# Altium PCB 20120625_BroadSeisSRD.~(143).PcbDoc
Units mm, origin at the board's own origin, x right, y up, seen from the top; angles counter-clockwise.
Board outline 68.5 x 51 mm, 4 copper layers (Top Layer, Mid-Layer 1, Mid-Layer 2, Bottom Layer); 59 components, 43 nets, 186 pads, 37 vias.
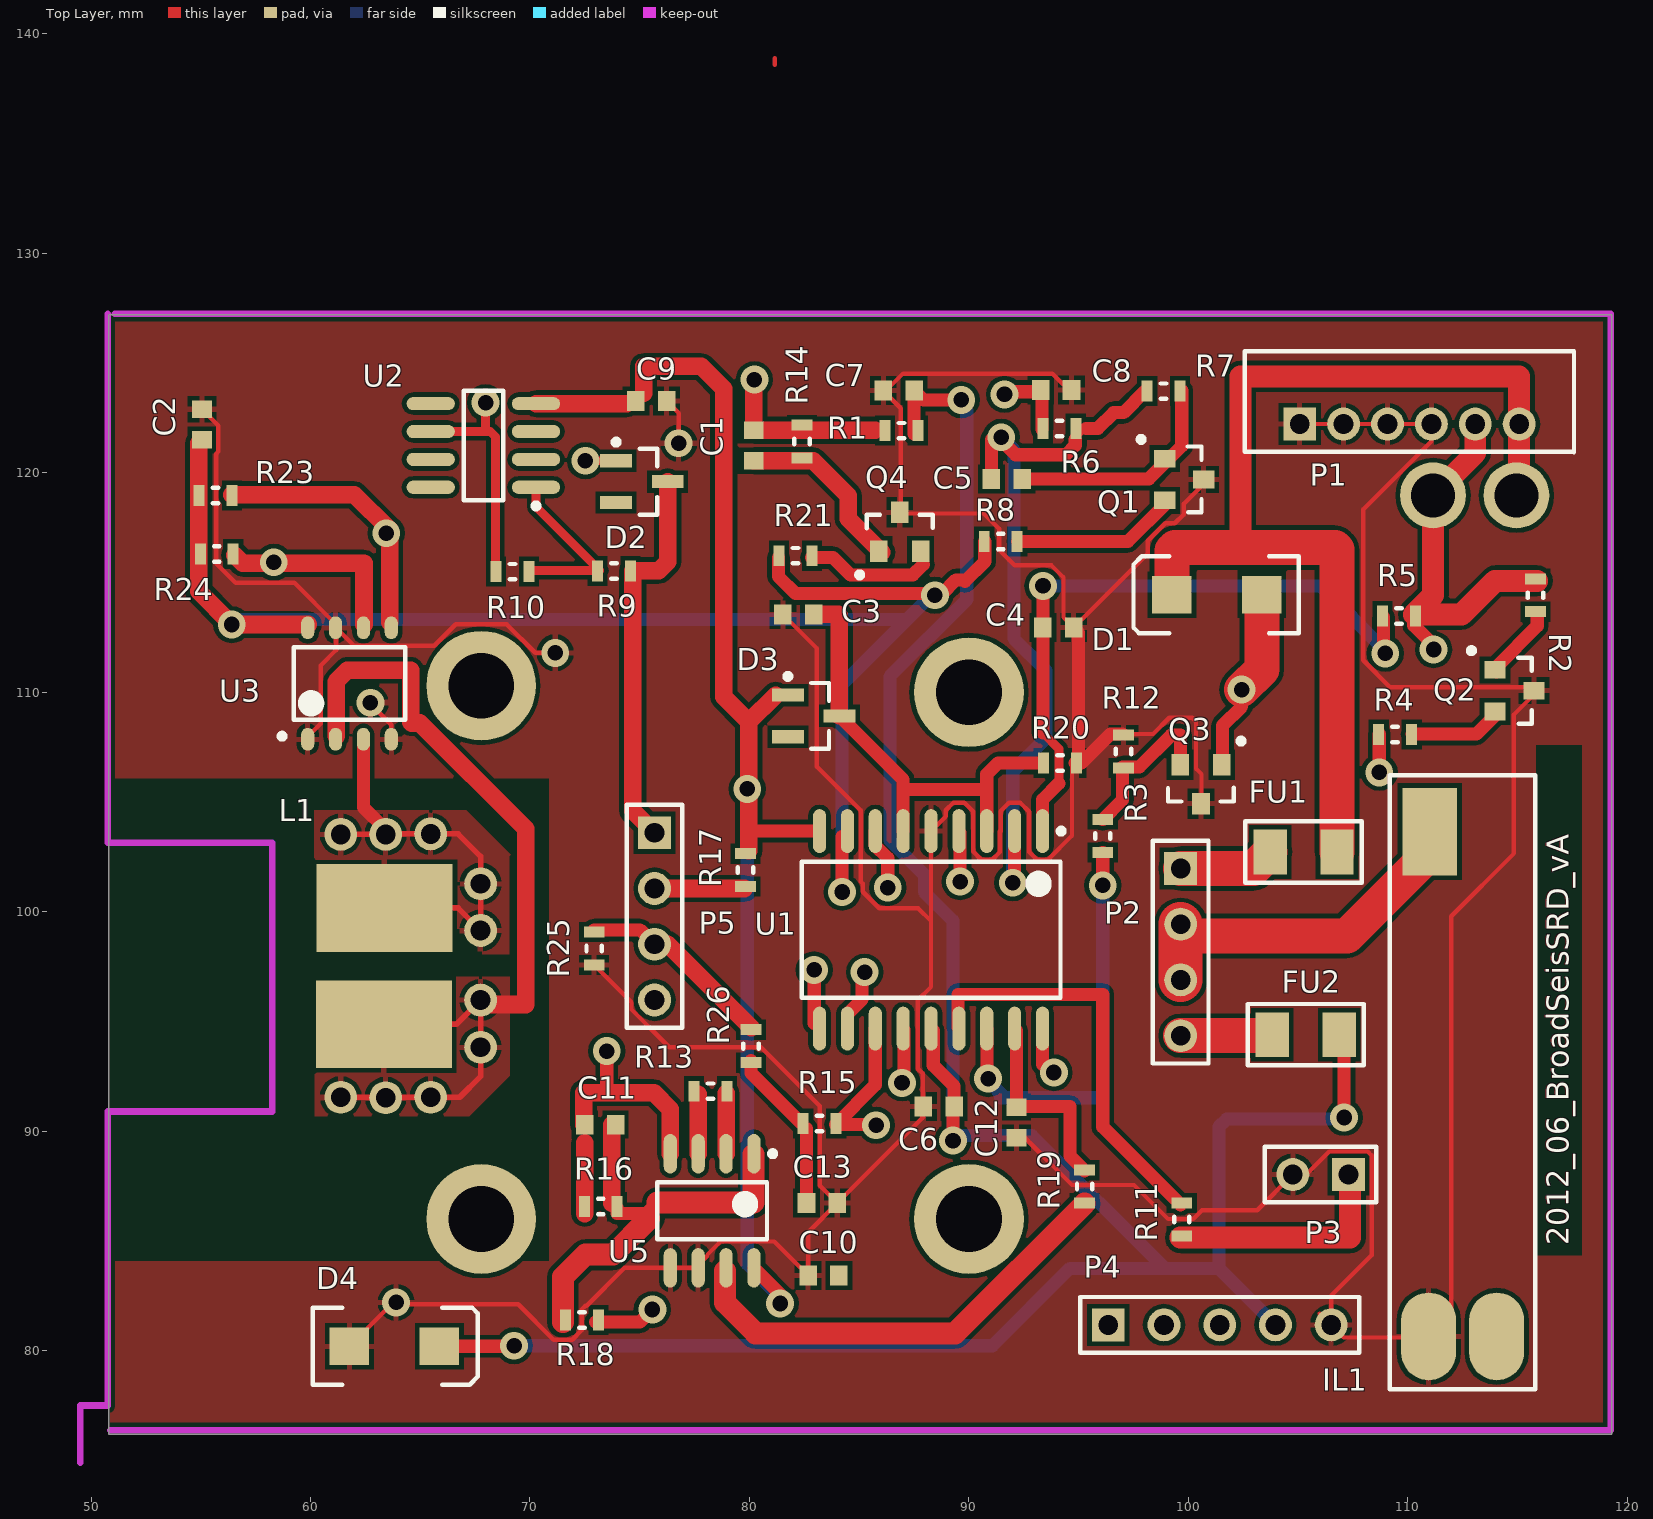
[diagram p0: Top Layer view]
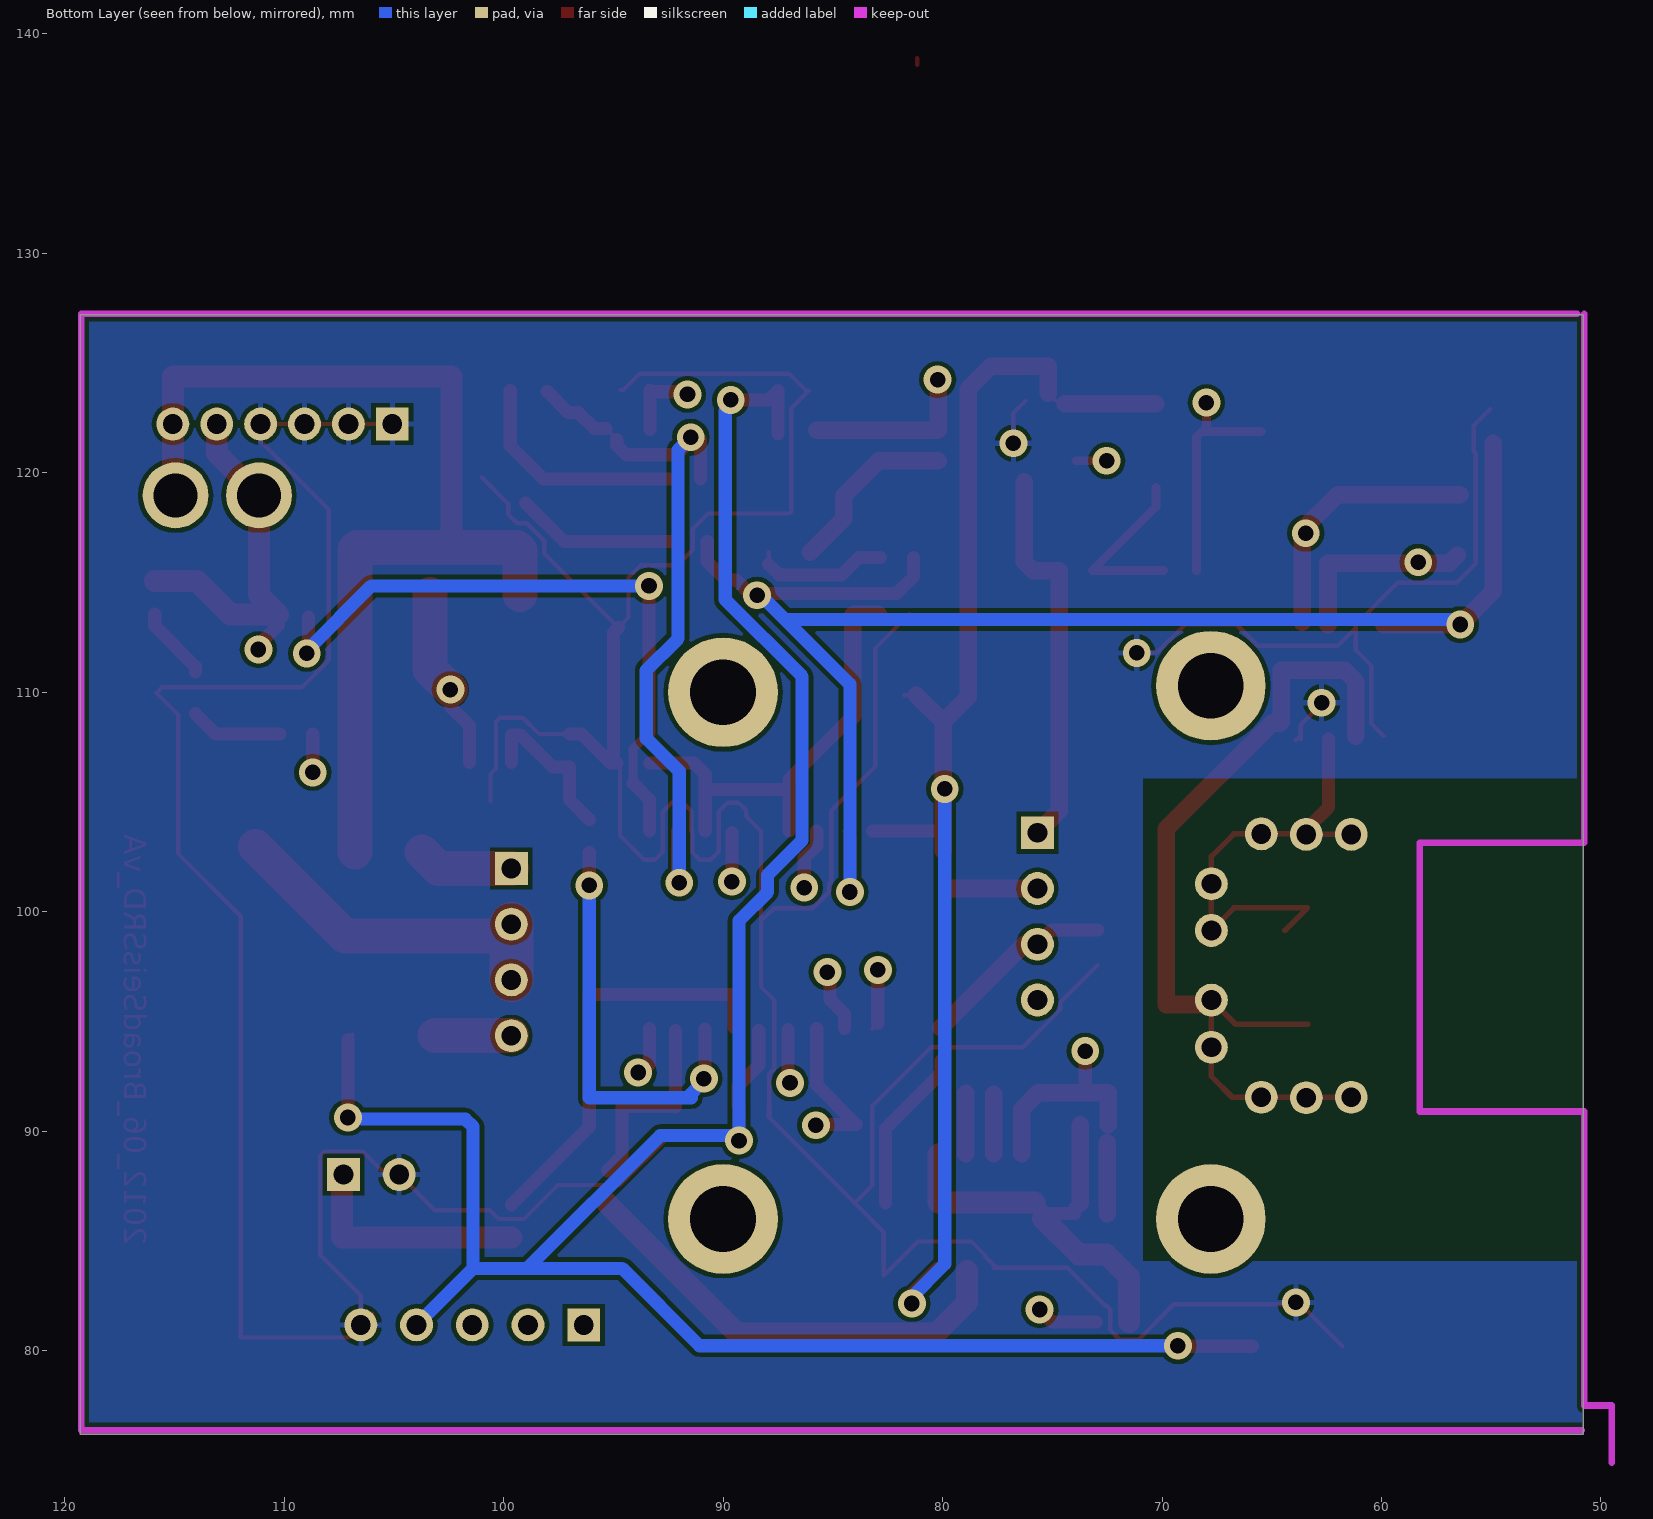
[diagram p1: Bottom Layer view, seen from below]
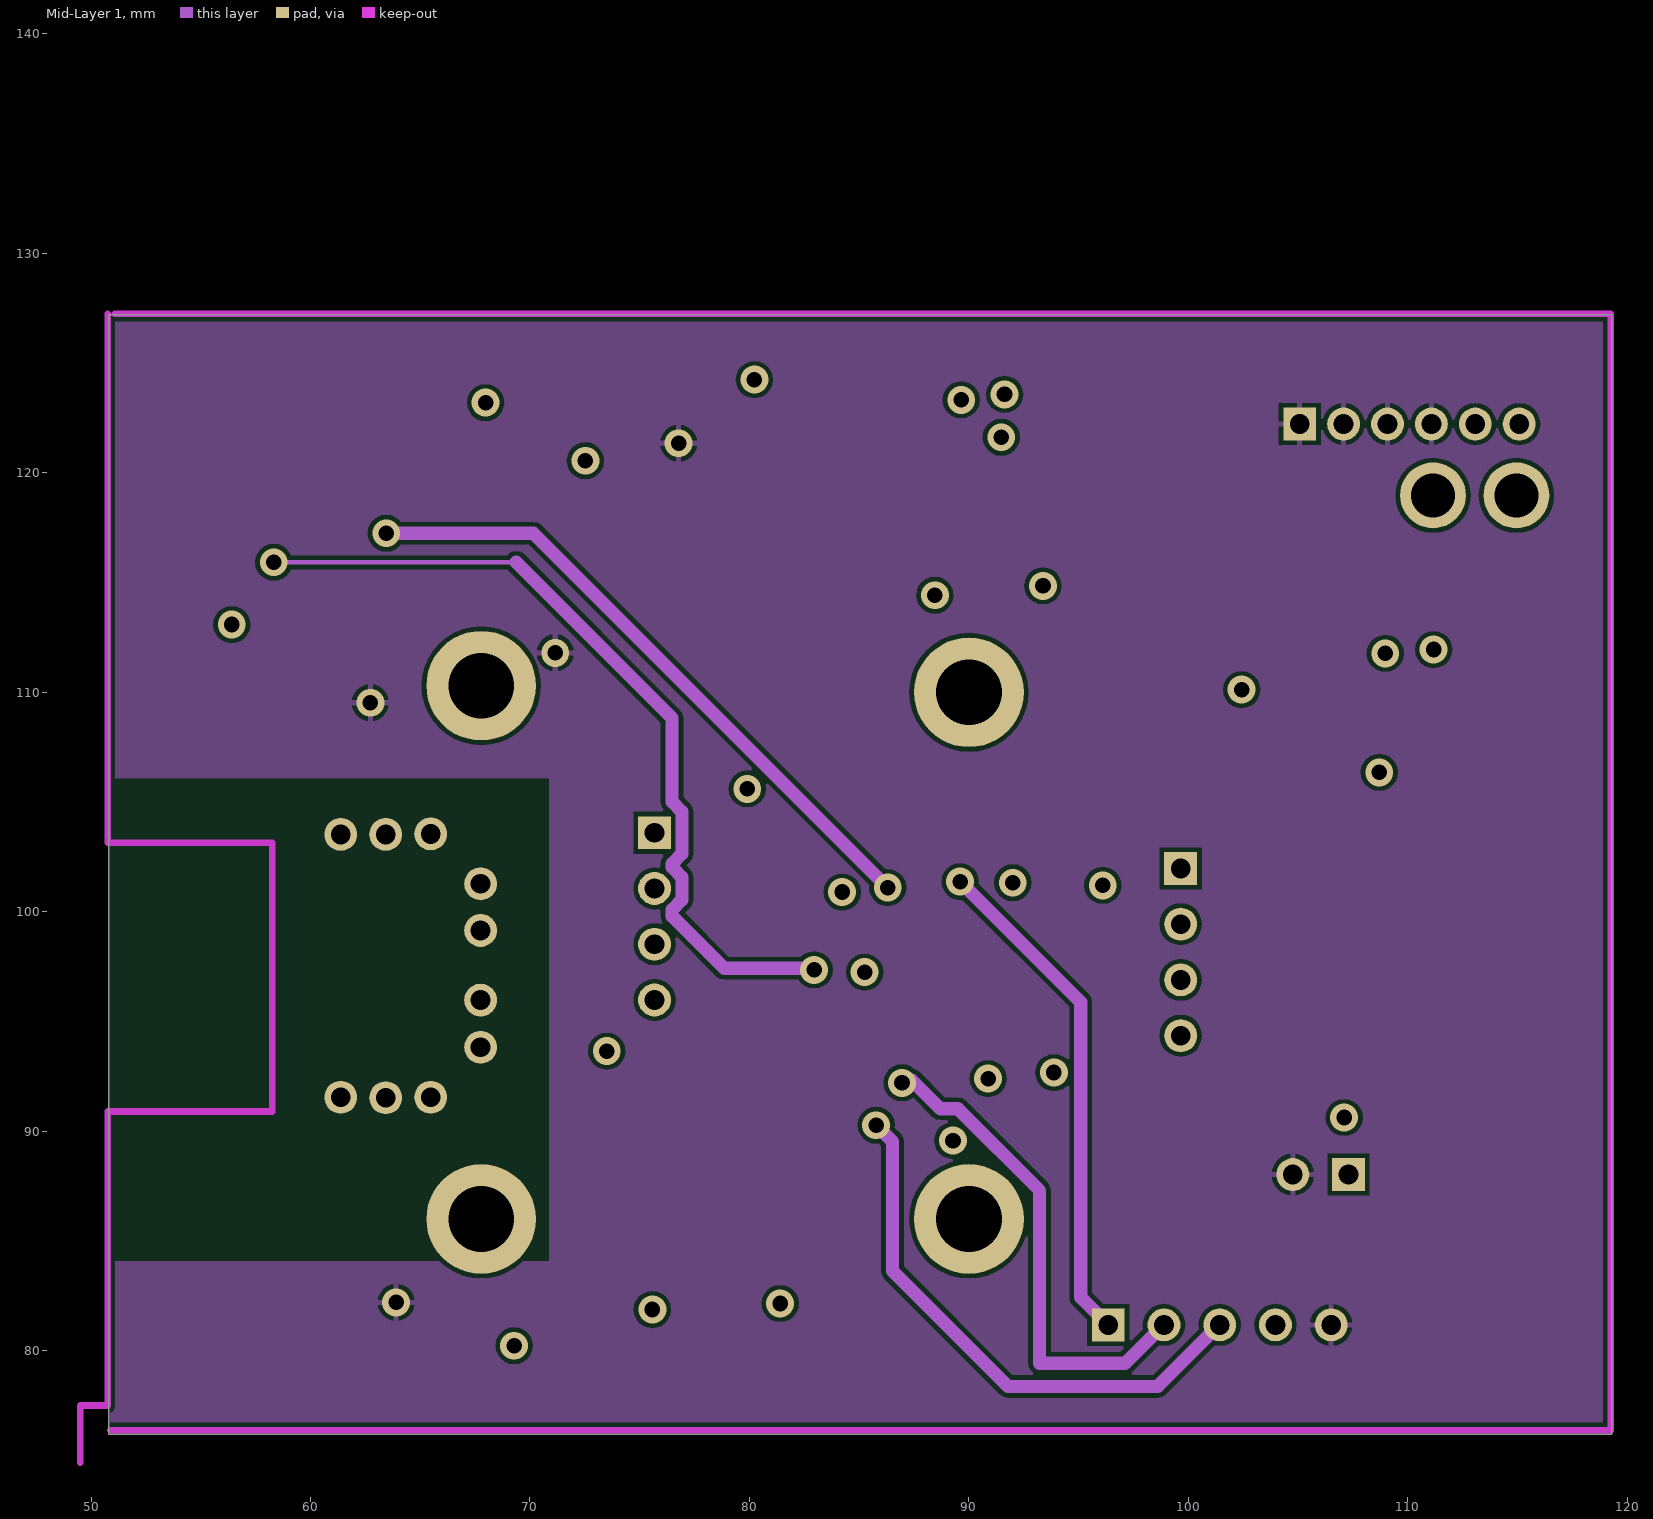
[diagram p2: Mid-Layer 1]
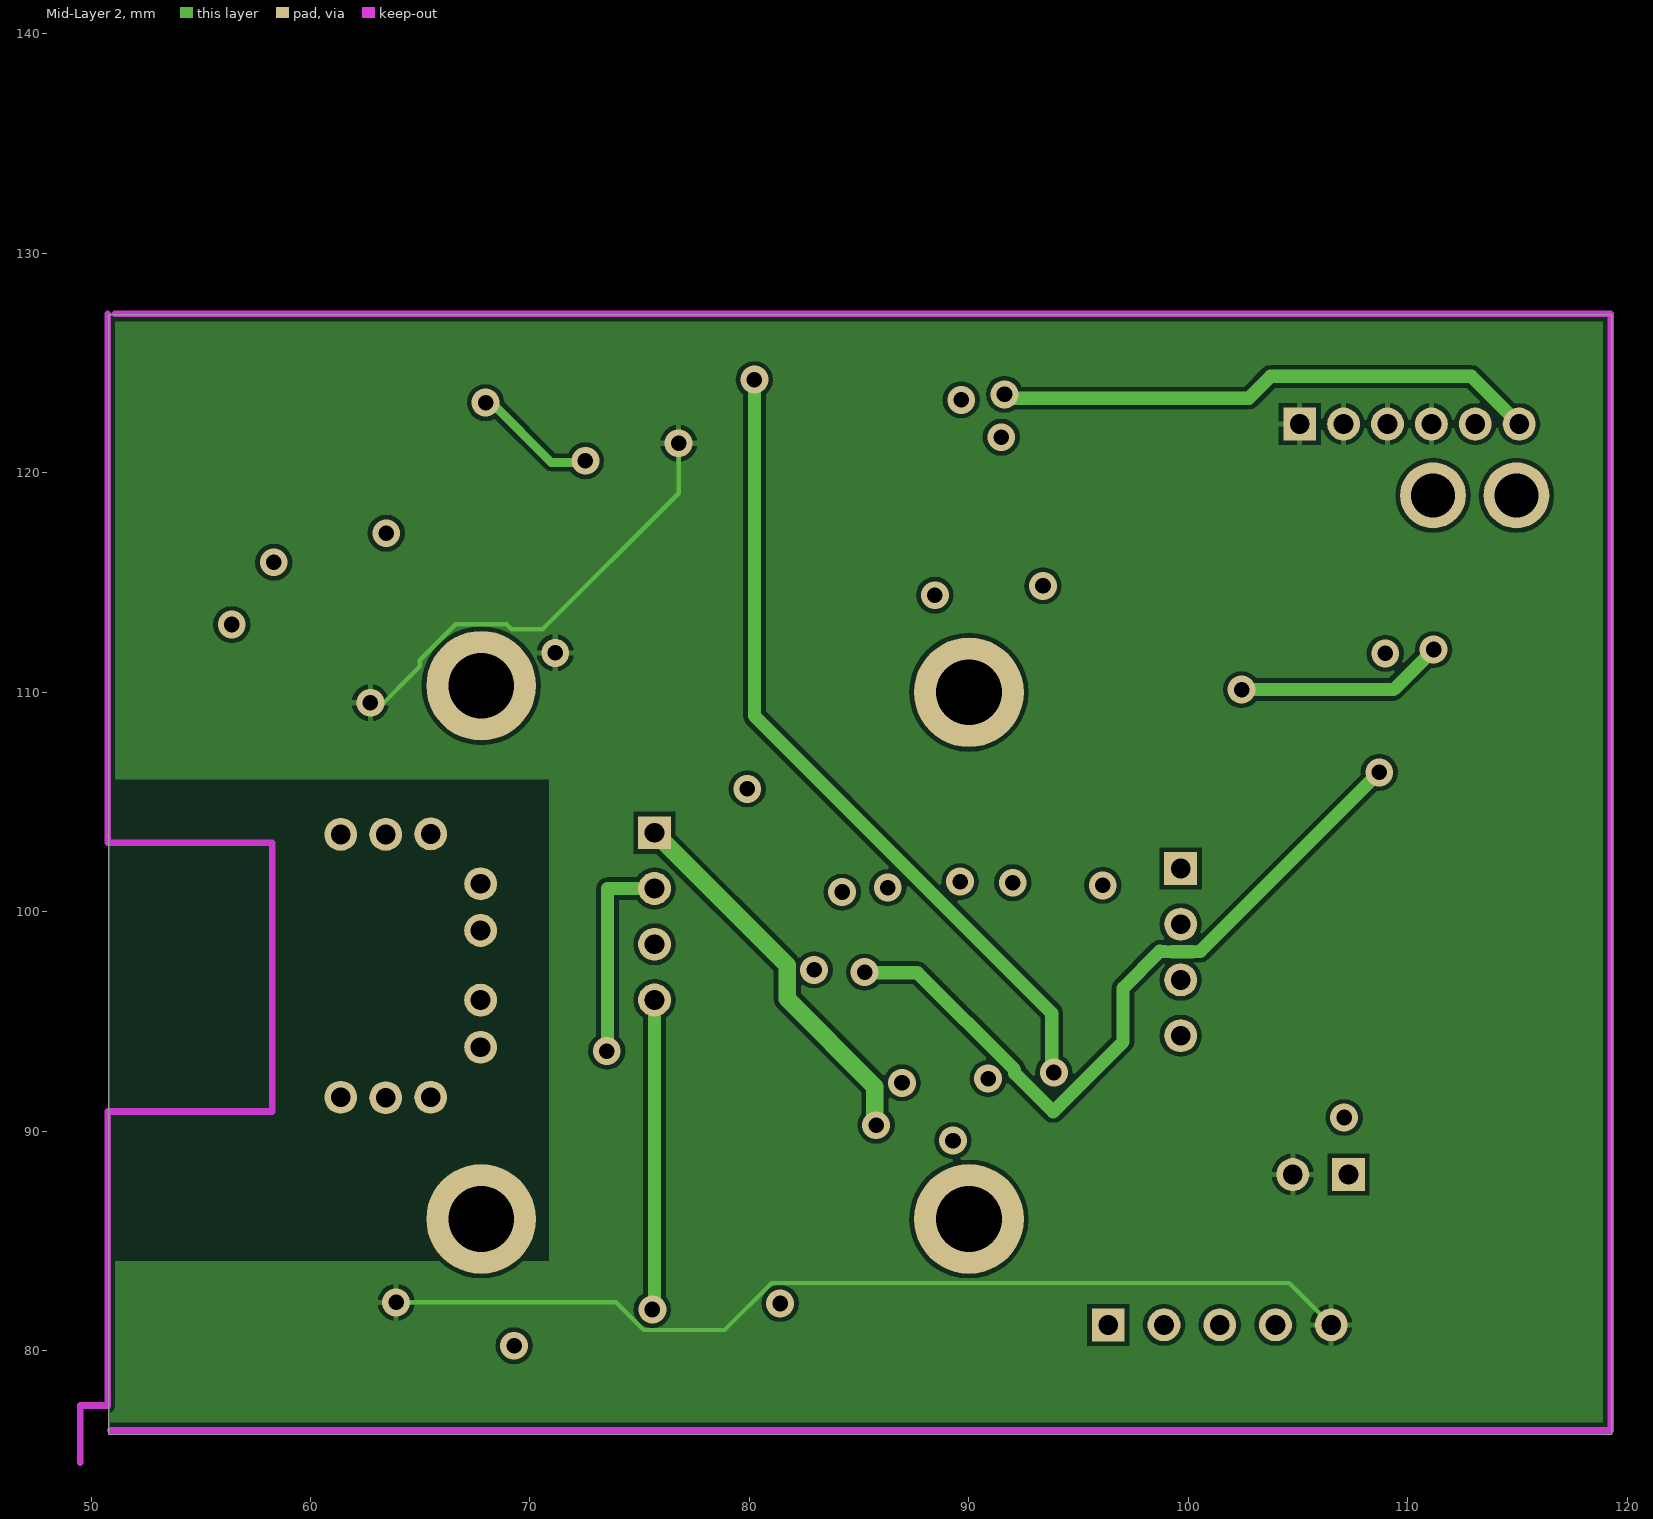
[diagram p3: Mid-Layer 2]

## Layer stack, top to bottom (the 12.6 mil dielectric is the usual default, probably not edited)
Top Layer: signal copper 0.0356
Dielectric: dielectric 0.32, FR-4, Dk 4.8
Mid-Layer 1: signal copper 0.0356
Dielectric: dielectric 0.32, FR-4, Dk 4.8
Mid-Layer 2: signal copper 0.0356
Dielectric: dielectric 0.32, FR-4, Dk 4.8
Bottom Layer: signal copper 0.0356

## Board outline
50.8,76.2 119.3,76.2 119.3,127.2 50.8,127.2

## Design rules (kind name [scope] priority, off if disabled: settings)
Clearance [All] p1: gap=0.2
HoleSize [All] p1: absolutevalues=TRUE maxlimit=5 minlimit=0.025 maxpercent=80.000 minpercent=20.000
PolygonConnect [All] p1: connectstyle=Relief reliefconductorwidth=0.254 reliefentries=4 polygonreliefangle="90 Angle"
RoomDefinition 2012_06_22_Sheet [InComponentClass('2012_06_22_Sheet')] p1: confinementstyle=ConfineIn formatcopy=TRUE lockcomponents=FALSE outline 49.281,128.725 49.412,128.593 121.35,128.593 121.35,74.737 121.114,74.5 49.15,74.5
RoutingVias [All] p1: holewidth=0.6 width=1 viastyle="Through Hole" minholewidth=0.711 minwidth=1.27 maxholewidth=0.711 maxwidth=1.27
SilkscreenOverComponentPads [All] p1: minsilkscreentomaskgap=0.254
SolderMaskExpansion [All] p1: expansion=0.102
Width [All] p1: maxlimit=2 minlimit=0.2 preferedwidth=0.6
26 further rules are at their usual default settings.

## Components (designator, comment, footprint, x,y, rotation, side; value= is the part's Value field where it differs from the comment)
C1 "Cap Semi" 1608[0603] 80.2,121.25 r90 top
C2 "Cap Semi" 1608[0603] 55.05,122.2 r270 top
C3 "Cap Semi" 1608[0603] 82.225,113.55 r0 top
C4 "Cap Semi" 1608[0603] 94.075,112.95 r180 top
C5 "Cap Semi" 1608[0603] 91.725,119.725 r180 top
C6 "Cap Semi" 1608[0603] 88.625,91.125 r0 top
C7 "Cap Semi" 1608[0603] 86.8,123.75 r0 top
C8 "Cap Semi" 1608[0603] 93.975,123.775 r180 top
C9 "Cap Semi" 1608[0603] 75.525,123.275 r180 top
C10 "Cap Semi" 1608[0603] 83.375,83.425 r0 top
C11 "Cap Semi" 1608[0603] 73.2,90.3 r180 top
C12 "Cap Semi" 1608[0603] 92.175,90.4 r90 top
C13 "Cap Semi" 1608[0603] 83.3,86.725 r180 top
D1 "RS1D" DiodeRS1D(recommendedfootprint) 101.3,114.45 r180 top
D2 "Diode BAS16" SOT-23_M 75.1,119.6 r0 top
D3 "Diode BAS16" SOT-23_M 82.925,108.925 r0 top
D4 "RS1D" DiodeRS1D(recommendedfootprint) 63.825,80.2 r0 top
FU1 "1A" FU(recommendedfootprint) 105.25,102.725 r0 top
FU2 "200mA" FU(recommendedfootprint) 105.35,94.4 r180 top
IL1 "ILS" ILS 113.95,103.65 r270 top
L1 "Inductor" INDC4532 63.375,97.525 r270 top
P1 "ConnectorToFB" "HIROSE DF3A-6P" 105.075,122.225 r0 top
P2 "Battery Pack pigtail" HDR1X4 99.65,101.975 r270 top
P3 "Connector to LED" HDR1X2 107.3,88.025 r180 top
P4 "Connector to Prog." HDR1X5 96.35,81.175 r0 top
P5 "Pressure Transducer pigtail" HDR1X4 75.675,103.6 r270 top
Q1 "NPN" transistor_SOT-23(recommendedfootprint) 99.9,119.7 r0 top
Q2 "NPN" transistor_SOT-23(recommendedfootprint) 114.95,110.075 r0 top
Q3 "MOSFET-IRLML" transistor_SOT-23(recommendedfootprint) 100.575,105.725 r270 top
Q4 "NPN" transistor_SOT-23(recommendedfootprint) 86.85,117.4 r90 top
R1 "Res3" J1-0603 86.925,121.925 r0 top
R2 "Res3" J1-0603 115.825,114.425 r90 top
R3 "Res3" J1-0603 96.1,103.45 r90 top
R4 "Res3" J1-0603 109.425,108.075 r0 top
R5 "Res3" J1-0603 109.6,113.475 r0 top
R6 "Res3" J1-0603 94.125,122.025 r180 top
R7 "Res3" J1-0603 98.875,123.725 r180 top
R8 "Res3" J1-0603 91.45,116.875 r0 top
R9 "Res3" J1-0603 73.825,115.525 r0 top
R10 "Res3" J1-0603 69.2,115.5 r180 top
R11 "Res3" J1-0603 99.7,85.975 r90 top
R12 "Res3" J1-0603 97.05,107.3 r270 top
R13 "Res3" J1-0603 78.225,91.825 r0 top
R14 "Res3" J1-0603 82.4,121.425 r90 top
R15 "Res3" J1-0603 83.2,90.35 r180 top
R16 "Res3" J1-0603 73.225,86.575 r180 top
R17 "Res3" J1-0603 79.825,101.9 r90 top
R18 "Res3" J1-0603 72.375,81.4 r180 top
R19 "Res3" J1-0603 95.275,87.475 r90 top
R20 "Res3" J1-0603 94.15,106.775 r180 top
R21 "Res3" J1-0603 82.1,116.225 r0 top
R23 "Res3" J1-0603 55.675,118.975 r0 top
R24 "Res3" J1-0603 55.725,116.3 r180 top
R25 "Res3" J1-0603 72.925,98.325 r90 top
R26 "Res3" J1-0603 80.075,93.875 r90 top
U1 "PIC16LF1827-I/SO" SOIC-SO18_L 88.275,99.175 r270 top
U2 "LM334D" SO8_N 67.875,121.25 r180 top
U3 "M24LR64" SO8N_N 61.775,110.4 r90 top
U5 "AD620BR" R-8D_N 78.3,86.375 r270 top

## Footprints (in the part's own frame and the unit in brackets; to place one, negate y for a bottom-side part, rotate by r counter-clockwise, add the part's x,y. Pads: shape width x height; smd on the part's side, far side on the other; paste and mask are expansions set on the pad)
1608[0603] [mm] "Chip Capacitor, Body 1.6x0.8mm, IPC High Density"
  rect 0.8x0.9 smd: 1(-0.7,0) 2(0.7,0)
  body extent -0.87,-0.48 0.87,0.48, height 1.3
DiodeRS1D(recommendedfootprint) [mm] "DO-214-AB/SMC; 2 C-Bend Leads; Body 7.9 x 5.9 mm, inc. leads (LxW)"
  rect 1.8x1.7 smd: 1(-2.05,0) 2(2.05,0)
  silkscreen extent -3.73,-1.75 3.8,1.75
FU(recommendedfootprint) [mm] "Thru-Hole; 2 Leads"
  rect 1.52x2.03 smd: 1(-1.525,0) 2(1.525,0)
  silkscreen extent -2.65,-1.4 2.65,1.4
HDR1X2 [mm] "Connector; Header; 2 Position"
  rect 1.5x1.5 hole 0.9: 1(0,0)
  round 1.5 hole 0.9: 2(2.54,0)
  silkscreen extent -1.27,-1.27 3.81,1.27
HDR1X4 [mm] "Connector; Header; 4 Position"
  rect 1.5x1.5 hole 0.9: 1(0,0)
  round 1.5 hole 0.9: 2(2.54,0) 3(5.08,0) 4(7.62,0)
  silkscreen extent -1.27,-1.27 8.89,1.27
HDR1X5 [mm] "Connector; Header; 5 Position"
  rect 1.5x1.5 hole 0.9: 1(0,0)
  round 1.5 hole 0.9: 2(2.54,0) 3(5.08,0) 4(7.62,0) 5(10.16,0)
  silkscreen extent -1.27,-1.27 11.43,1.27
"HIROSE DF3A-6P" [mm] "Connector; Header; 6 Position"
  rect 1.5x1.5 hole 0.9: 1(0,0)
  round 1.5 hole 0.9: 2(2,0) 3(4,0) 4(6,0) 5(8,0) 6(10,0)
  round 3 hole 2: 5(6.075,-3.25) 6(9.875,-3.25)
  Top Layer lines w0.254: 9.875,-3.25 10,-2.75
  Top Layer lines w1: 6.075,-3.25 8,-1.325 8,0 ; 10,-2.75 10,0
  silkscreen extent -2.5,-1.29 12.5,3.32
ILS [mm]
  rect 4x2.5 smd: 1(0,-2.95)
  oval 4x2.5 smd: 2(23,-3) 3(23,0.1)
  silkscreen extent -2.58,-4.77 25.4,1.85
INDC4532 [mm] "Chip Inductor, Body 4.5x3.2mm, IPC High Density"
  round 1.5 hole 0.9: 1(-6.025,2.1) 1(-6,0.05) 1(-6,-2) 1(-3.75,4.375) 1(-1.625,4.375) 2(1.55,4.375) 2(3.7,4.375) 2(5.975,2.1) 2(5.975,-2) 2(6,0.05)
  rect 4x6.2 smd: 1(-2.65,0) 2(2.65,-0.025)
  Top Layer lines w0.254: -6,-2 -6,0.05 -6.025,0.075 -6.025,2.1 -6.025,3.35 -5,4.375 -3.75,4.375 -1.625,4.375 -2.65,3.35 -2.65,0 -1.625,1.025
J1-0603 [mm] "Chip Resistor, Body 1.6x0.8mm, IPC High Density"
  rect 0.5x0.95 smd: 1(-0.75,0) 2(0.75,0)
  silkscreen extent -0.13,-0.35 0.13,0.35, body extent -0.85,-0.48 0.85,0.48, height 0.9
R-8D_N [mm] "SOIC, 8-Leads, Body 4.9x3.9mm, Pitch 1.27mm, IPC Medium Density"
  oval 1.8x0.6 smd: 1(-2.6,1.905) 2(-2.6,0.635) 3(-2.6,-0.635) 4(-2.6,-1.905) 5(2.6,-1.905) 6(2.6,-0.635) 7(2.6,0.635) 8(2.6,1.905)
  silkscreen extent -2.72,-2.5 1.3,2.88, body extent -2,-2.5 2,2.5, height 2.59
SO8_N [mm] "SOIC, 8-Leads, Body 4.9x3.9mm, Pitch 1.27mm, IPC Medium Density"
  oval 2.2x0.6 smd: 1(-2.4,1.905) 2(-2.4,0.635) 3(-2.4,-0.635) 4(-2.4,-1.905) 5(2.4,-1.905) 6(2.4,-0.635) 7(2.4,0.635) 8(2.4,1.905)
  silkscreen extent -2.53,-2.5 0.9,2.88, body extent -1.95,-2.45 1.95,2.45, height 1.75
SO8N_N [mm] "SOP, 8-Leads, Body 5.3x5.3mm, Pitch 1.27mm, IPC Medium Density"
  oval 1.04x0.6 smd: 1(-2.54,1.905) 2(-2.54,0.635) 3(-2.54,-0.635) 4(-2.54,-1.905) 5(2.54,-1.905) 6(2.54,-0.635) 7(2.54,0.635) 8(2.54,1.905)
  silkscreen extent -2.52,-2.54 1.65,3.2, body extent -2.29,-2.54 2.29,2.54, height 2.13
SOIC-SO18_L [mm] "SOIC, 18-Leads, Body 11.5x7.5mm, Pitch 1.27mm, IPC High Density"
  oval 2x0.6 smd: 1(-4.5,5.08) 2(-4.5,3.81) 3(-4.5,2.54) 4(-4.5,1.27) 5(-4.5,0) 6(-4.5,-1.27) 7(-4.5,-2.54) 8(-4.5,-3.81) 9(-4.5,-5.08) 10(4.5,-5.08) 11(4.5,-3.81) 12(4.5,-2.54) 13(4.5,-1.27) 14(4.5,0) 15(4.5,1.27) 16(4.5,2.54) 17(4.5,3.81) 18(4.5,5.08)
  silkscreen extent -4.62,-5.9 3.1,6.06, body extent -3.8,-5.95 3.8,5.95, height 2.65
SOT-23_M [mm] "SOT23, 3-Leads, Body 2.9x1.3mm, Pitch 0.95mm, Lead Span 2.5mm, IPC Low Density"
  rect 1.45x0.6 smd: 1(-1.175,0.95) 2(-1.175,-0.95) 3(1.175,0)
  silkscreen extent -1.3,-1.5 0.7,1.92, body extent -0.7,-1.5 0.7,1.5, height 1.1
transistor_SOT-23(recommendedfootprint) [mm] "SOT23, 3-Leads, Body 2.9x1.3mm, Pitch 0.95mm, Lead Span 2.5mm, IPC Low Density"
  rect 0.972x0.802 smd: 1(-0.975,0.95) 2(-0.975,-0.95) 3(0.8,0)
  silkscreen extent -2.17,-1.5 0.7,1.95, body extent -0.7,-1.5 0.7,1.5, height 1.1

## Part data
C1 C2 C3 C4 C5 C6 C7 C8 C9 C10 C11 C12 C13: "Capacitor (Semiconductor SIM Model)"
D1 D4: library part Diode, "Default Diode"
D2 D3: "Silicon Switching Diode for High-Speed Switching"
FU1 FU2: library part "Fuse 1", "Fuse"
IL1: "SPDT Subminiature Toggle Switch, Right Angle Mounting, Vertical Actuation"
P1: "Header, 6-Pin"
P2 P5: "Header, 4-Pin"
P3: "Header, 2-Pin"
P4: "Header, 5-Pin"
Q1 Q2 Q4: "NPN Bipolar Transistor"
Q3: "N-Channel MOSFET"
R1 R2 R3 R4 R5 R6 R7 R8 R9 R10 R11 R12 R13 R14 R15 R16 R17 R18 R19 R20 R21 R23 R24 R25 R26: "Resistor"
U1: "EPROM-Based 8-Bit CMOS Microcontroller, 25 Bytes RAM, 4 MHz, 18-Pin SOIC, 3.0 to 5.5V Supply Range, Extended Temperature"
U2: "Three Terminal Adjustable Current Source"
U3: "32 Kbit Serial I²C Bus EEPROM"
U5: "Low-Cost, Low-Power Instrumentation Amplifier"

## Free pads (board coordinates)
  round 5 hole 3: 1(67.775,86) 1(67.775,110.3) 1(90,86) 1(90,110)

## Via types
v1: diameter 1.27, hole 0.711, Top Layer to Bottom Layer, 37 vias

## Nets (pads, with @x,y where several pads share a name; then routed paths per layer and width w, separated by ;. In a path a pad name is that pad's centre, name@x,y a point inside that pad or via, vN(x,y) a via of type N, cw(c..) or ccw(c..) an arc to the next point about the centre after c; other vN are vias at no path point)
ACTIVATION+: FU1.1 P2.1 | length 4.4
  Top Layer w1.6: P2.1 102.975,101.975 FU1.1
ANA_PRESSURE: C12.2 R19.2 U1.17 | length 9.3
  Top Layer w0.2: U1.17 U1.17@92.175,94.585 ; C12.2 C12.2@92.2,91.125
  Top Layer w0.6: C12.2 U1.17@92.175,94.585 ; C12.2@92.2,91.125 94.6,91.125 94.6,88.875 R19.2@95.275,88.2
B7: P4.2 U1.13 | length 25.1
  Top Layer w0.2: U1.13 U1.13@87.05,94.63
  Top Layer w0.6: v1(86.954,92.204) 86.954,92.454 87.05,92.55 U1.13@87.05,94.63
  Mid-Layer 1 w0.6: v1@86.95,92.325 87.4,92.325 88.7,91.025 89.5,91.025 93.225,87.3 93.225,79.425 97.115,79.425 P4.2@98.878,81.187
CHECK-FIRE: R4.1 U1.11 | length 38.6
  Top Layer w0.2: v1@85.135,97.135 v1(85.25,97.25)
  Top Layer w0.6: U1.11 84.465,95.34 85.135,96.01 v1@85.135,97.135 ; v1(108.7,106.35) R4.1@108.7,108.1
  Mid-Layer 2 w0.6: v1@85.325,97.225 87.655,97.225 92.085,92.795 92.085,92.64 93.838,90.887 97.025,94.075 97.025,96.525 98.7,98.2 99.262,98.175 100.187,98.175 100.55,98.2 v1(108.7,106.35)
COIL1: L1.1 U3.3 | length 4.8
  Top Layer w0.254: L1.1@63.425,103.525 L1.1@63.425,103.75
  Top Layer w0.6: U3.3 62.41,104.765 L1.1@63.425,103.75
COIL2: L1.2 U3.2 | length 40.9
  Top Layer w0.2: 61.165,110.49 61.2,110.525
  Top Layer w0.254: L1.2@61.375,91.55 65.475,91.55 66.8,91.55 67.75,92.5 67.75,93.825 67.75,95.975 66.65,94.875 L1.2@63.35,94.875
  Top Layer w0.8: U3.2@61.165,108.01 61.165,110.49 ; 61.2,110.525 61.675,111 64.575,111 64.575,108.633 64.605,108.603 64.972,108.603 69.8,103.775 69.8,95.775 67.95,95.775 L1.2@67.75,95.975
FB1: C8.2 D1.2 FU1.2 P1.6 R6.2 | length 75.1
  Top Layer w0.2: 99.25,116.45 99.4,116.6 ; 102.325,116.6 102.375,116.65 ; 106.675,116.6 106.775,116.5
  Top Layer w0.6: v1(91.625,123.575) 91.45,123.575 91.375,123.5 91.6,123.5 91.8,123.7 C8.2@93.275,123.7 ; R6.2@93.325,121.975 C8.2@93.325,123.775
  Top Layer w1: 102.375,116.65 102.375,124.4 115.075,124.4 P1.6@115.075,122.225
  Top Layer w1.6: D1.2 99.25,116.45 ; 99.4,116.6 102.325,116.6 106.675,116.6 ; FU1.2 106.775,116.5
  Mid-Layer 2 w0.6: v1@91.65,123.775 92.025,123.4 102.75,123.4 103.75,124.4 112.9,124.4 P1.6@115.075,122.225
FB2: D1.1 P1.5 Q3.1 R2.2 R5.2 | length 31.7
  Top Layer w0.6: Q3.1@101.55,106.8 101.55,108.475 102.425,109.35 v1(102.425,110.125) ; R5.2@110.275,113.55 110.275,113.05 v1@111.175,112.15
  Top Layer w1: P1.5@111.15,118.975 111.15,114.425 110.275,113.55 112.45,113.55 113.975,115.075 R2.2@115.9,115.075
  Top Layer w1.6: v1(102.425,110.125) 103.35,111.05 D1.1
  Mid-Layer 2 w0.6: v1(102.425,110.125) 109.35,110.125 v1(111.175,111.95)
FIRE: R3.1 U1.16 | length 19.8
  Top Layer w0.2: U1.16 U1.16@90.825,94.665
  Top Layer w0.6: U1.16@90.825,94.665 90.825,92.15 90.9,92.225 90.95,92.225 90.875,92.3 v1(90.875,92.4) ; v1(96.1,101.2) R3.1
  Bottom Layer w0.6: v1@90.825,92.15 90.9,92.225 90.95,92.225 91.575,91.6 ; 91.45,91.525 96.1,91.525 v1(96.1,101.2)
FLASH_LED: R11.2 U1.15 | length 19.2
  Top Layer w0.2: U1.15@89.5,94.72 U1.15
  Top Layer w0.6: U1.15@89.5,94.72 89.5,96.225 96.1,96.225 96.1,90.2 R11.2@99.65,86.65
GND: C2.1 C3.1 C4.1 C6.1 C7.1 C8.1 C9.1 C10.1 C12.1 C13.1 D4.1 IL1.2 P1.1 P1.2 P1.3 P1.4 P3.2 P4.5 Q1.3 Q2.3 Q3.3 Q4.3 R12.1 R20.1 R25.1 U1.5 U3.1 U3.4 U3.7 U5.5 U5.6 | length 348
  Top Layer w0.2: C2.1 55.8,122.15 55.8,120.976 55.7,120.876 55.7,115.876 56.586,114.99 59.265,114.99 61.165,113.09 U3.7@61.165,112.94 ; U3.1@59.895,108.01 60.465,108.58 60.465,111.225 61.165,111.925 U3.7@61.165,112.94 ; D4.1 63.687,82.113 69.463,82.113 71.076,80.5 71.924,80.5 72.35,80.926 72.35,81.874 72.526,82.05 72.581,82.05 74.306,83.775 U5.5 77.535,83.775 U5.6@77.6,83.84 ; v1@62.575,109.325 62.875,109.325 63.68,108.52 U3.4 ; U3.4@63.705,108.01 U3.4@63.9,107.815 ; v1(71.15,111.8) 70.235,111.8 68.935,113.1 66.615,113.1 65.635,112.12 61.985,112.12 U3.7@61.165,112.94 ; R25.1 74.625,95.875 74.625,95.545 76.345,93.825 80.524,93.825 83.2,91.149 83.2,87.525 C13.1 ; C9.1 76.775,122.725 v1(76.775,121.35) ; U5.6@77.6,83.775 U5.6@77.6,83.84 ; U5.6 U5.6@77.6,83.84 ; C3.1 83.075,112 83.075,106.614 85.065,104.624 85.065,101.382 85.16,101.287 85.16,100.918 85.913,100.165 87.685,100.165 88.275,99.575 ; 87.925,90.65 C6.1 C6.1@87.889,91.089 ; C12.1@92.075,89.8 C12.1 92.551,89.7 94.701,87.55 97.526,87.55 99.076,86 100.224,86 100.624,86.4 103.135,86.4 P3.2 105.376,88.025 106.426,89.075 108.174,89.075 108.35,88.899 108.35,84.35 106.51,82.51 P4.5 ; C8.1 94.549,123.775 93.799,124.525 87.001,124.525 86.226,123.75 C7.1 86.9,122.95 86.9,118.225 86.975,118.15 90.674,118.15 91.375,117.449 91.375,116.501 92.091,115.785 93.762,115.785 94.31,115.237 94.31,113.415 C4.1 98.15,116.325 98.15,116.906 98.944,117.7 99.386,117.7 99.786,118.1 99.786,118.586 Q1.3@101,119.8 ; R20.1@95,106.925 94.85,106.775 94.7,106.625 94.7,103.471 93.604,102.375 93.106,102.375 92.755,102.726 92.755,104.554 92.334,104.975 91.836,104.975 91.45,104.589 91.45,103.675 91.415,103.675 91.415,102.726 91.064,102.375 90.566,102.375 90.2,102.741 90.2,104.569 89.794,104.975 89.296,104.975 88.945,104.624 88.945,104.345 U1.5 88.275,99.575 ; R12.1@97,108.1 98.389,108.1 99.125,108.836 100.175,108.836 100.351,108.66 100.351,106.524 100.6,106.275 Q3.3@100.6,105.025 ; P1.1 P1.2 P1.3 P1.4 111.075,121.446 107.965,118.336 107.965,111.463 109.204,110.224 115.576,110.224 115.825,109.975 114.836,108.986 114.836,102.661 111.975,99.8 111.975,80.6 107.085,80.6 P4.5 ; P4.5@105.99,81.695 P4.5 ; U5.6@77.6,83.84 78.091,84.331 78.091,84.379 78.686,84.975 81.125,84.975 C10.1 82.675,85.4 C13.1 ; C13.1 87.875,90.6 87.875,91.075 C6.1@87.889,91.089 ; C6.1@87.889,91.089 87.889,92.637 87.675,92.851 87.675,95.975 88.275,96.575 88.275,99.575
  Top Layer w0.6: C4.1 95,112.725 R20.1@95,106.925 ; R20.1@94.85,106.775 95.125,106.775 96.45,108.1 R12.1@97,108.1
  Mid-Layer 2 w0.2: v1@62.575,109.325 62.875,109.325 63,109.2 64.975,111.175 64.975,111.46 66.615,113.1 68.935,113.1 69.16,112.875 70.575,112.875 76.775,119.075 v1(76.775,121.35) v1@76.775,121.65 ; v1(63.9,82.2) 73.928,82.2 75.188,80.94 78.868,80.94 81.013,83.085 104.6,83.085 P4.5
  other v1: 62.725,109.525
IN+: D2.3 P4.3 P5.1 R9.2 R15.1 U1.12 | length 67.5
  Top Layer w0.2: v1@85.75,90.3 v1(85.775,90.275)
  Top Layer w0.6: U1.12 85.735,92.11 83.925,90.3 v1@85.75,90.3
  Top Layer w0.8: P5.1 74.675,104.6 74.675,115.55 75.875,115.55 76.275,115.95 D2.3
  Mid-Layer 1 w0.6: v1(85.775,90.275) 86.525,89.525 86.525,83.625 91.775,78.375 98.605,78.375 P4.3@101.418,81.187
  Mid-Layer 2 w0.8: P5.1 81.715,97.56 81.715,96.038 85.719,92.034 85.719,90.331 v1(85.775,90.275)
IN-: P5.3 R25.2 R26.2 | length 8.4
  Top Layer w0.6: R25.2@72.925,99.175 75.02,99.175 P5.3
  Top Layer w0.8: P5.3@76.28,98.52 R26.2@80.075,94.725
LED+: P3.1 R11.1 | length 10.6
  Top Layer w1: R11.1@99.65,85.15 107.375,85.15 107.375,87.95 P3.1
LP0-VDD: C2.2 R8.1 R21.1 R23.1 R24.2 U1.8 U3.8 | length 74.1
  Top Layer w0.2: C2.2@54.9,121.35 C2.2 ; U1.8@84.225,103.435 U1.8
  Top Layer w0.6: R21.1@81.325,116.15 81.325,115.275 82.1,114.5 88.784,114.5 89.409,115.125 89.741,115.125 89.816,115.05 90.725,115.959 R8.1@90.725,116.875 ; v1(84.225,100.9) U1.8@84.225,103.435
  Top Layer w0.8: C2.2@54.9,121.35 54.9,119 54.9,116.4 54.9,114.6 v1(56.41,113.09) U3.8@59.895,113.09
  Bottom Layer w0.2: v1(56.41,113.09) v1@56.645,113.325
  Bottom Layer w0.6: v1@56.645,113.325 87.175,113.325 ; v1(84.225,100.9) 84.225,110.375 v1@88.575,114.725
  other v1: 88.45,114.425
LP1-VDD: C9.2 D3.1 R17.2 U1.9 U2.4 U5.8 | length 63.4
  Top Layer w0.2: C9.2 C9.2@75.175,123.625 ; 79.975,103.725 80.025,103.675 ; D3.1@81.2,109.875 D3.1 ; v1@81.475,82.505 81.475,82.35 81.65,82.175 v1@81.65,82.125
  Top Layer w0.6: 80.025,103.675 U1.9 ; U5.8 v1@81.475,82.505
  Top Layer w0.8: U2.4 74.405,123.155 ; C9.2@75.175,123.625 75.175,124.85 77.8,124.85 78.825,123.825 78.825,109.8 79.975,108.65 ; R17.2@79.975,102.775 79.975,103.725 79.975,108.65 ; D3.1@81.2,109.875 79.975,108.65
  Bottom Layer w0.2: v1@81.475,82.375 v1@81.7,82.15
  Bottom Layer w0.6: v1(79.9,105.6) 79.9,83.95 v1@81.475,82.375
  other v1: 81.4,82.15
LP1_VDD: C10.2
MCLR/: P4.1 U1.4 | length 25.3
  Top Layer w0.2: U1.4 U1.4@89.6,103.62
  Top Layer w0.6: v1(89.6,101.375) U1.4@89.6,103.62
  Mid-Layer 1 w0.6: v1(89.6,101.375) 95.1,95.875 95.1,82.425 P4.1
NetC1_1: C1.1 Q4.1 R14.1 | length 8.2
  Top Layer w0.8: C1.1 82.9,120.55 84.5,118.95 84.5,117.9 Q4.1@86.025,116.375
NetC3_2: C3.2 D3.3 R20.2 U1.3 U1.6 | length 21.3
  Top Layer w0.2: 84.05,113.55 84.1,113.5
  Top Layer w0.6: D3.3 87.005,106.02 87.005,105.525 ; U1.6 87.005,105.525 ; 90.74,105.575 87.055,105.575 87.005,105.525 ; U1.3 90.815,106.265 91.325,106.775 R20.2@93.35,106.775
  Top Layer w0.8: C3.2 84.05,113.55 ; D3.3 84.1,113.5
NetC5_1: C5.1 Q1.1 R7.1 | length 10.4
  Top Layer w0.6: C5.1 98.2,119.725 99,120.525 99.7,121.225 R7.1@99.7,123.75
NetC11_1: C11.1 R16.1 R18.2 U5.1 | length 19.8
  Top Layer w0.2: R16.1@73.725,86.725 R16.1@73.975,86.475
  Top Layer w0.6: R16.1@73.975,86.475 73.975,86.25 75.3,86.25 75.8,86.75
  Top Layer w0.8: R16.1@73.725,86.725 C11.1@73.725,90.3
  Top Layer w1: R18.2@71.5,81.3 71.5,83.35 72.525,84.375 73.775,84.375 75.425,86.025 ; 75.8,86.75 80.175,86.75 U5.1@80.175,88.945
NetC13_2: C13.2 R15.2 R26.1 | length 7.5
  Top Layer w0.2: R15.2@82.425,90.3 R15.2@82.6,90.125
  Top Layer w0.6: R26.1@80.075,93.225 80.075,92.65 R15.2@82.425,90.3 ; C13.2 R15.2@82.6,90.125
NetD2_1: D2.1 R10.2 U2.6 | length 17.4
  Top Layer w0.4: U2.6 68.19,121.885 68.425,121.65 R10.2@68.425,115.55 ; 67.975,121.96 v1(67.975,123.2) ; v1(72.525,120.55) D2.1
  Mid-Layer 2 w0.4: v1@67.95,123.2 v1(67.975,123.2) 68.25,123.2 70.975,120.475 72.325,120.475 72.35,120.45 v1@72.35,120.425
NetIL1_1: IL1.1 P2.2 P2.3 | length 16.1
  Top Layer w0.2: P2.2 100.185,98.9
  Top Layer w1.6: 100.185,98.9 107.225,98.9 IL1.1@111.3,102.975
  Top Layer w2: P2.3 P2.2
NetQ1_2: Q1.2 R8.2 | length 7.5
  Top Layer w0.6: R8.2@92.225,116.875 97.25,116.875 Q1.2@99,118.625
NetQ2_1: Q2.1 R2.1 | length 3.4
  Top Layer w0.6: Q2.1@114.05,110.925 114.05,111.175 115.9,113.025 R2.1@115.9,113.575
NetQ2_2: Q2.2 R4.2 | length 4.2
  Top Layer w0.6: R4.2@110.2,108.1 113.125,108.1 Q2.2@114.05,109.025
NetQ3_2: Q3.2 R3.2 R12.2 | length 7.3
  Top Layer w0.6: R3.2 97,105.1 97,106.6 97.775,106.6 99.225,108.05 99.65,108.05 Q3.2@99.65,106.8
NetQ4_2: Q4.2 R21.2 | length 6.2
  Top Layer w0.2: 87.925,115.825 Q4.2@87.925,116.375
  Top Layer w0.6: R21.2@82.825,116.15 83.8,116.15 84.6,115.35 87.45,115.35 87.925,115.825
NetR9_1: R9.1 R10.1 U2.1 | length 8.2
  Top Layer w0.4: R10.1@69.925,115.55 73.175,115.55 70.275,118.45 U2.1
NetR13_1: R13.1 U5.3 | length 2.7
  Top Layer w0.8: U5.3 R13.1@77.665,91.685
NetR13_2: R13.2 U5.2 | length 2.8
  Top Layer w0.8: U5.2 R13.2@78.935,91.735
NetR19_1: R19.1 U5.7 | length 20.9
  Top Layer w1: U5.7@78.891,83.641 78.891,82.184 80.285,80.79 89.365,80.79 R19.1@95.275,86.7
OUT+: C11.2 P5.2 R16.2 R17.1 U5.4 | length 26.4
  Top Layer w0.6: 73.5,91.87 v1(73.5,93.65)
  Top Layer w0.8: C11.2@72.45,90.3 72.45,91.75 75.65,91.75 76.395,91.005 U5.4 ; R16.2@72.5,86.25 72.5,89.475 ; P5.2 R17.1@79.76,101.06
  Mid-Layer 2 w0.2: v1(73.5,93.65) v1@73.535,93.685
  Mid-Layer 2 w0.6: v1@73.535,93.685 73.535,101.06 P5.2
OUT-: P5.4 R18.1 | length 18
  Top Layer w0.2: v1(75.575,81.875) 75.875,81.875 v1@75.725,82.025
  Top Layer w0.6: R18.1@73,81.3 75,81.3 v1@75.725,82.025
  Mid-Layer 2 w0.2: v1(75.575,81.875) 75.875,81.875 v1@75.675,82.075
  Mid-Layer 2 w0.6: v1@75.675,82.075 P5.4
PCB+: FU2.2 P2.4 | length 3.5
  Top Layer w1.6: P2.4 FU2.2@103.12,94.355
SCLK: R24.1 U1.10 U3.6 | length 50.1
  Top Layer w0.2: U1.10@82.95,94.92 U1.10
  Top Layer w0.6: U1.10@82.95,94.92 v1(82.95,97.35)
  Top Layer w0.8: R24.1@56.55,116.25 56.915,115.885 62.435,115.885 U3.6@62.435,113.09
  Mid-Layer 1 w0.2: v1(58.325,115.925) 69.375,115.925
  Mid-Layer 1 w0.6: 69.375,115.925 76.475,108.825 76.475,105.007 76.925,104.557 76.925,102.643 76.475,102.193 76.475,102.028 76.925,101.578 76.925,100.542 76.475,100.092 76.475,99.8 78.85,97.425 v1@83.15,97.425
SDA: R23.2 U1.7 U3.5 | length 44.1
  Top Layer w0.6: U1.7 85.735,103.015 86.3,102.45 v1(86.3,101.1)
  Top Layer w0.8: R23.2@56.4,119 62,119 63.6,117.4 U3.5@63.6,113.195
  Mid-Layer 1 w0.6: v1(63.45,117.25) 70.15,117.25 v1@86.05,101.35
VBAT1: C1.2 R1.1 R14.2 U1.18 | length 46.9
  Top Layer w0.6: U1.18 93.355,93.045 v1@93.575,92.825
  Top Layer w0.8: v1@80.2,124.025 C1.2 85.725,121.95
  Mid-Layer 2 w0.6: v1(80.225,124.25) 80.225,108.925 93.775,95.375 v1@93.775,92.55
  other v1: 93.875,92.675
VBAT2: C5.2 R6.1 R7.2 U1.2 | length 34.9
  Top Layer w0.2: v1@91.025,121.525 90.95,121.6 90.975,121.625 v1(91.475,121.625) v1@91.475,121.475 ; 94.85,121.525 95.35,122.025
  Top Layer w0.6: C5.2 v1@91.025,121.525 ; v1@91.475,121.475 92.125,120.825 94.425,120.825 94.85,121.25 94.85,121.525 ; v1(92,101.325) 92.085,101.41 U1.2 ; 95.35,122.025 95.875,122.025 96.6,122.75 97.05,122.75 R7.2@98.012,123.712
  Bottom Layer w0.6: v1(91.475,121.625) 92.05,121.05 92.05,112.45 93.5,111 93.5,107.9 92,106.4 v1(92,101.325)
VDD: C6.2 C7.2 D4.2 FU2.1 P4.4 R1.2 U1.14 | length 115
  Top Layer w0.2: v1@69.25,80.2 v1(69.275,80.225) ; U1.14 U1.14@88.375,94.575 ; C6.2@89.275,91.075 C6.2 ; FU2.1 FU2.1@107.1,94.175
  Top Layer w0.6: D4.2 v1@69.25,80.2 ; R1.2@87.5,121.775 C7.2 87.925,123.325 v1(89.65,123.325) ; U1.14@88.375,94.575 88.375,93 89.325,92.05 C6.2 ; v1(89.275,89.575) C6.2@89.275,91.075 ; v1(107.1,90.625) FU2.1@107.1,94.175
  Bottom Layer w0.2: v1(89.275,89.575) v1@89.275,89.8 ; v1(89.65,123.325) 89.425,123.325 v1@89.9,122.85
  Bottom Layer w0.6: v1(69.275,80.225) 91.075,80.225 94.6,83.75 98.92,83.75 ; v1@89.9,122.85 89.9,114.225 86.4,110.725 86.4,103.253 87.975,101.678 87.975,100.9 89.275,99.6 89.275,89.8 92.87,89.8 98.92,83.75 ; P4.4 101.395,83.75 ; 106.45,90.55 101.74,90.55 101.395,90.205 101.395,83.75 ; 98.92,83.75 101.395,83.75
VFIRE: C4.2 R5.1 U1.1 | length 30.6
  Top Layer w0.2: R5.1@108.775,113.55 R5.1@108.9,113.425
  Top Layer w0.4: 93.375,108.15 94.1,107.425 94.1,105.85
  Top Layer w0.6: U1.1 93.355,105.105 94.1,105.85 ; 93.375,108.15 C4.2 v1(93.375,114.85) ; R5.1@108.9,113.425 108.9,111.85 v1(108.975,111.775)
  Bottom Layer w0.6: v1(93.375,114.85) 106.025,114.85 108.975,111.9 v1(108.975,111.775)
pads on no net: D2.2 D3.2 IL1.3 U2.2 U2.3 U2.5 U2.7 U2.8
copper on no net: | length 0.3
  Top Layer w0.2: 81.15,138.6 81.15,138.9

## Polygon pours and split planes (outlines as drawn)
GND on Top Layer "Top Layer-No Net" (solid, pour order 33): 50.875,76.375 50.875,84.075 70.875,84.075 70.875,106.075 50.875,106.075 50.75,106.2 50.75,127.25 119.25,127.25 119.25,76.375
COIL2 on Top Layer "Top Layer-No Net" (solid, pour order 28): 60.2,90.675 66.925,90.675 67.225,90.675 69.075,92.525 69.075,97.05 60.175,97.05
COIL1 on Top Layer "Top Layer-No Net" (solid, pour order 26): 60.175,104.625 66.725,104.625 67.1,104.625 69.125,102.6 69.05,102.525 69.05,98.075 60.175,98.075 60.125,98.025
GND on Mid-Layer 1 "Top Layer-No Net" (solid, pour order 35): 50.75,127.25 119.25,127.25 119.25,76.375 50.875,76.375 50.875,84.075 70.875,84.075 70.875,106.075 50.875,106.075
GND on Mid-Layer 2 "Top Layer-No Net" (solid, pour order 37): 50.75,127.25 119.25,127.25 119.25,76.375 50.875,76.375 50.875,84.075 70.875,84.075 70.875,106.05 50.875,106.05
GND on Bottom Layer "Top Layer-No Net" (solid, pour order 41): 50.75,127.25 119.25,127.25 119.25,76.375 50.875,76.375 50.875,84.075 70.875,84.075 70.875,106.075 50.875,106.075

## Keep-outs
Keep-Out Layer:
  lines w0.3: 49.5,76.325 49.5,74.9 49.5,77.5 50.75,77.5 50.75,90.9 58.25,90.9 58.25,97.1 58.25,103.15 50.75,103.15 50.75,108.837 50.75,109.862 50.75,117.8 50.75,127.25 ; 50.875,76.375 119.25,76.375 119.25,127.25 51.075,127.25

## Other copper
Top Layer:
  text "2012_06_BroadSeisSRD_vA" at 117.3,84.8 h1 r90

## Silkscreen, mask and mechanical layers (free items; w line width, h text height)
Top Overlay:
  text "2012_06_BroadSeisSRD_vA" at 117.325,84.8 h1 r90
Drill Drawing:
  text ".LEGEND" at 128.952,79.739 h1.52
  text "Drill Drawing." at 128.952,77.199 h1.52

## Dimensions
50.8,76.2 to 50.75,77.5 on Mechanical 1
50.75,77.5 to 49.45,76.375 on Mechanical 1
